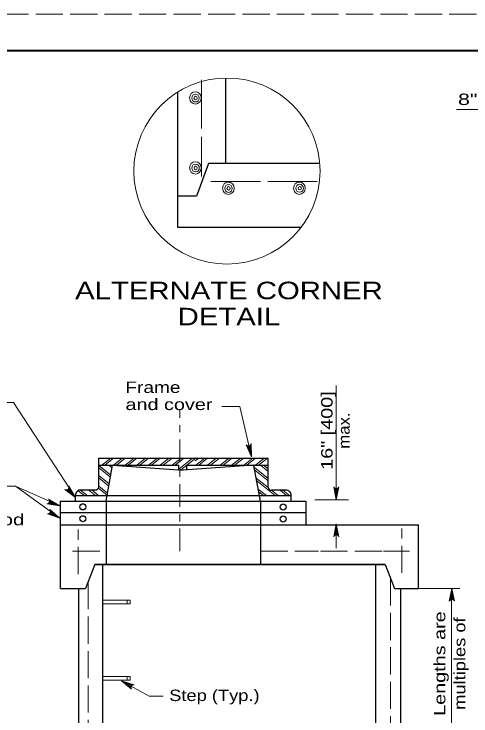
# Model space of a CAD drawing. Extents: x 808.4 to 842.4, y 1034.6 to 1056.6.
# Drawn here: x 819.59 to 825.84, y 1047.01 to 1056.63 of the extents above; entities that cross this region are included whole.
import ezdxf
from ezdxf.enums import TextEntityAlignment as Align

# ---------------------------------------------------------------- set-up
doc = ezdxf.new("R2010")
doc.units = 0
doc.header["$LTSCALE"] = 0.062
doc.linetypes.add('DOT_DASHED', pattern=[7.7, 5, -1.2, 0.3, -1.2])
doc.linetypes.add('LONG_DASHED', pattern=[7.5, 6, -1.5])
doc.layers.add('1', color=7, linetype='Continuous', lineweight=13)
doc.layers.add('10', color=7, linetype='Continuous')

msp = doc.modelspace()

# ---------------------------------------------------------------- linework, layer by layer
at = {"layer": '1', "lineweight": 25}
for p, q in [((822.48142, 1055.75075), (822.48142, 1054.58133)), ((821.82408, 1055.556), (821.82408, 1053.70467)), ((822.48142, 1054.82217), (822.48142, 1054.58133)), ((822.24892, 1054.58133), (822.08375, 1054.1305)), ((822.85492, 1054.58133), (822.24892, 1054.58133)), ((823.77225, 1054.58133), (822.48142, 1054.58133)), ((822.08375, 1054.1305), (821.82958, 1054.1305)), ((821.82408, 1053.70467), (823.517, 1053.70467)), ((820.74533, 1050.14633), (820.74533, 1050.54133)), ((820.74533, 1050.54133), (823.06542, 1050.54133)), ((823.0645, 1050.14258), (823.0645, 1050.54133)), ((820.74533, 1050.445), (821.84467, 1050.445)), ((821.84467, 1050.38208), (821.84467, 1050.445)), ((822.86458, 1050.445), (821.89917, 1050.37792)), ((822.96125, 1049.95075), (822.87183, 1050.44158)), ((820.50092, 1050.1055), (820.69875, 1050.1055)), ((823.30892, 1050.10175), (823.11108, 1050.10175)), ((820.427, 1049.95842), (820.427, 1050.03075)), ((820.427, 1050.03075), (823.38283, 1050.03075)), ((823.38283, 1049.95842), (823.38283, 1050.03075)), ((820.21808, 1049.95408), (820.21808, 1049.62825)), ((820.21808, 1049.95408), (823.58258, 1049.95408)), ((820.846, 1049.9495), (820.84842, 1049.4435)), ((822.96125, 1049.95075), (822.96125, 1049.62825)), ((823.58258, 1049.95075), (823.58258, 1049.62825)), ((820.21808, 1049.79442), (823.58142, 1049.79442)), ((820.21808, 1049.62825), (823.58258, 1049.62825)), ((820.22408, 1049.62808), (824.64392, 1049.62808)), ((822.9615, 1049.62042), (822.9615, 1049.0825)), ((824.64392, 1049.62808), (825.12575, 1049.62808)), ((820.84842, 1049.4435), (820.84842, 1049.09175)), ((820.69325, 1049.0825), (820.56483, 1048.75375)), ((820.69325, 1049.0825), (824.66783, 1049.0825)), ((820.7995, 1049.0825), (820.7995, 1040.04192)), ((824.53808, 1049.0825), (824.53808, 1040.04192)), ((824.66783, 1049.0825), (824.79625, 1048.75375)), ((824.66792, 1049.08242), (824.79625, 1048.75375)), ((820.22408, 1048.75375), (820.56483, 1048.75375)), ((820.47083, 1048.75375), (820.47083, 1046.71117)), ((824.79625, 1048.75375), (825.12575, 1048.75375)), ((824.8835, 1046.71117), (824.88358, 1048.75375))]:
    msp.add_line(p, q, dxfattribs=at)
at = {"layer": '1'}
for p, q in [((822.15117, 1055.72725), (822.15117, 1055.06108)), ((822.15117, 1054.94658), (822.15117, 1054.4015)), ((822.9605, 1054.33233), (822.28067, 1054.33233)), ((823.73567, 1054.33233), (823.06217, 1054.33233)), ((823.99867, 1051.53733), (823.99867, 1049.97233)), ((822.68008, 1051.2515), (822.43017, 1051.2515)), ((822.83842, 1050.56), (822.68008, 1051.2515)), ((822.78167, 1050.71158), (822.83842, 1050.56)), ((822.79367, 1050.70867), (822.83842, 1050.56)), ((822.80508, 1050.7095), (822.83842, 1050.56)), ((822.8185, 1050.71542), (822.83842, 1050.56)), ((822.82733, 1050.72367), (822.83842, 1050.56)), ((820.90933, 1050.54125), (820.78817, 1050.445)), ((820.94875, 1050.53933), (820.83, 1050.445)), ((821.06717, 1050.54075), (820.94658, 1050.445)), ((821.10975, 1050.54133), (820.98842, 1050.445)), ((821.22925, 1050.54125), (821.108, 1050.445)), ((821.26867, 1050.53933), (821.14983, 1050.445)), ((821.387, 1050.54075), (821.26642, 1050.445)), ((821.42958, 1050.54133), (821.30825, 1050.445)), ((821.549, 1050.54125), (821.42775, 1050.445)), ((821.58842, 1050.53933), (821.46967, 1050.445)), ((821.70683, 1050.54075), (821.58625, 1050.445)), ((821.74933, 1050.54133), (821.62808, 1050.445)), ((821.87325, 1050.54117), (821.752, 1050.44492)), ((821.91267, 1050.53925), (821.79392, 1050.44492)), ((822.03108, 1050.54067), (821.84467, 1050.39267)), ((822.07367, 1050.54125), (821.87067, 1050.38008)), ((822.11375, 1050.53883), (822.068, 1050.50258)), ((822.19767, 1050.54117), (822.0765, 1050.44492)), ((822.23708, 1050.53925), (822.11833, 1050.44492)), ((822.3555, 1050.54067), (822.23492, 1050.44492)), ((822.39808, 1050.54125), (822.27675, 1050.44492)), ((822.52317, 1050.53875), (822.402, 1050.4425)), ((822.56258, 1050.53692), (822.44383, 1050.4425)), ((822.681, 1050.53825), (822.56042, 1050.4425)), ((822.72358, 1050.53883), (822.60225, 1050.4425)), ((822.85542, 1050.54125), (822.73417, 1050.445)), ((822.89483, 1050.53933), (822.77608, 1050.445)), ((823.01325, 1050.54075), (822.89267, 1050.445)), ((823.05575, 1050.54133), (822.9345, 1050.445)), ((820.74533, 1050.44125), (820.91167, 1050.30933)), ((820.88175, 1050.44417), (820.92883, 1050.40675)), ((820.92208, 1050.44417), (820.93442, 1050.43442)), ((822.96092, 1050.44375), (823.06375, 1050.36217)), ((823.00008, 1050.4445), (823.0645, 1050.39325)), ((820.74533, 1050.40808), (820.90633, 1050.28017)), ((822.87733, 1050.4115), (823.06508, 1050.26233)), ((822.88392, 1050.37533), (823.06508, 1050.2315)), ((820.74533, 1050.303), (820.88958, 1050.18858)), ((820.74558, 1050.26967), (820.88433, 1050.15942)), ((822.9035, 1050.268), (823.06483, 1050.13983)), ((820.21375, 1049.7195), (819.60567, 1050.15742)), ((820.74658, 1050.1575), (820.86692, 1050.06208)), ((822.9125, 1050.229), (823.16283, 1050.03017)), ((820.3015, 1050.10658), (820.42717, 1050.00117)), ((820.31333, 1050.10883), (820.42717, 1050.00117)), ((820.326, 1050.11617), (820.42717, 1050.00117)), ((820.33342, 1050.12492), (820.42717, 1050.00117)), ((820.33817, 1050.13633), (820.42717, 1050.00117)), ((820.46267, 1050.0955), (820.5425, 1050.03208)), ((820.49167, 1050.10567), (820.58667, 1050.03025)), ((820.61, 1050.10433), (820.70292, 1050.0305)), ((820.64942, 1050.10617), (820.74417, 1050.031)), ((820.741, 1050.12875), (820.86075, 1050.03367)), ((822.93067, 1050.11808), (823.04133, 1050.03025)), ((822.93758, 1050.08083), (823.00083, 1050.03067)), ((823.11342, 1050.10117), (823.20283, 1050.03017)), ((823.22958, 1050.10075), (823.31842, 1050.03017)), ((823.26675, 1050.10208), (823.35733, 1050.03017)), ((823.97625, 1050.13258), (823.99867, 1049.97233)), ((823.98733, 1050.12717), (823.99867, 1049.97233)), ((824.0235, 1050.1345), (823.99867, 1049.97233)), ((824.01308, 1050.12833), (823.99867, 1049.97233)), ((823.99867, 1050.1255), (823.99867, 1049.97233)), ((820.07067, 1049.96342), (820.21367, 1049.88767)), ((823.70383, 1049.97233), (824.16483, 1049.97233)), ((820.05283, 1049.91975), (820.21367, 1049.88767)), ((820.06208, 1049.92742), (820.21367, 1049.88767)), ((820.06967, 1049.93992), (820.21367, 1049.88767)), ((820.072, 1049.95117), (820.21367, 1049.88767)), ((820.06067, 1049.77833), (820.21375, 1049.7195)), ((820.07108, 1049.78433), (820.21375, 1049.7195)), ((820.08075, 1049.79542), (820.21375, 1049.7195)), ((820.08492, 1049.80608), (820.21375, 1049.7195)), ((820.08567, 1049.81842), (820.21375, 1049.7195)), ((823.97392, 1049.48), (823.99867, 1049.64217)), ((823.98433, 1049.48617), (823.99867, 1049.64217)), ((823.99867, 1049.489), (823.99867, 1049.64217)), ((824.01, 1049.48733), (823.99867, 1049.64217)), ((824.02108, 1049.48192), (823.99867, 1049.64217)), ((823.99867, 1049.64217), (823.99867, 1049.30933)), ((824.97742, 1048.75675), (825.69158, 1048.75675)), ((825.19625, 1048.75675), (825.69158, 1048.75675)), ((825.55725, 1048.59492), (825.582, 1048.757)), ((825.56767, 1048.601), (825.582, 1048.757)), ((825.5775, 1048.75675), (825.5775, 1046.73775)), ((825.582, 1048.60383), (825.582, 1048.757)), ((825.59333, 1048.60225), (825.582, 1048.757)), ((825.60442, 1048.59683), (825.582, 1048.757)), ((820.79992, 1048.59592), (821.178, 1048.59592)), ((820.79992, 1048.543), (821.178, 1048.543)), ((821.13425, 1048.54217), (821.13425, 1048.59508)), ((821.178, 1048.543), (821.178, 1048.59592)), ((820.79992, 1047.54975), (821.178, 1047.54975)), ((820.79992, 1047.49675), (821.178, 1047.49675)), ((821.19217, 1047.41658), (821.05833, 1047.49117)), ((821.18767, 1047.40267), (821.05833, 1047.49117)), ((821.18792, 1047.39058), (821.05833, 1047.49117)), ((821.19908, 1047.42567), (821.05833, 1047.49117)), ((821.20925, 1047.43275), (821.05833, 1047.49117)), ((821.05833, 1047.49117), (821.43758, 1047.27942)), ((821.13408, 1047.49658), (821.13408, 1047.5495)), ((821.178, 1047.49675), (821.178, 1047.54975)), ((821.43758, 1047.27933), (821.62633, 1047.27933))]:
    msp.add_line(p, q, dxfattribs=at)
at = {"layer": '1', "linetype": 'DOT_DASHED'}
msp.add_line((821.85792, 1049.26533), (821.85792, 1051.19467), dxfattribs=at)
at = {"layer": '1', "linetype": 'LONG_DASHED'}
for p, q in [((820.38767, 1049.26492), (820.847, 1049.26492)), ((822.9615, 1049.26492), (823.75675, 1049.26492)), ((823.782, 1049.26492), (824.64392, 1049.26492)), ((824.64392, 1049.26492), (825.00358, 1049.26492)), ((820.59942, 1048.84225), (820.59942, 1044.61292)), ((824.74183, 1048.89308), (824.74183, 1044.64242))]:
    msp.add_line(p, q, dxfattribs=at)
msp.add_lwpolyline([(808.43883, 1034.62767), (842.43883, 1034.62767), (842.43883, 1056.62767), (808.43883, 1056.62767)], close=True, dxfattribs=at)
at = {"layer": '1', "lineweight": 25}
msp.add_lwpolyline([(810.43883, 1056.12767), (841.93883, 1056.12767), (841.93883, 1035.12767), (810.43883, 1035.12767)], close=True, dxfattribs=at)
at = {"layer": '1', "lineweight": 40}
msp.add_lwpolyline([(810.43883, 1056.12767), (841.93883, 1056.12767), (841.93883, 1035.12767), (810.43883, 1035.12767)], close=True, dxfattribs=at)
at = {"layer": '1'}
for points in [[(825.64475, 1055.31858), (829.13883, 1055.31858), (831.39858, 1055.31858)], [(820.42717, 1050.00117), (819.57933, 1051.30342), (819.32275, 1051.30342)], [(822.83442, 1050.7405), (822.83842, 1050.56), (822.76533, 1050.72508)], [(820.21367, 1049.88767), (819.60567, 1050.15742), (819.29283, 1050.15742)], [(820.28367, 1050.11075), (820.42717, 1050.00117), (820.33683, 1050.1575)], [(824.03408, 1050.14933), (823.99867, 1049.97233), (823.96333, 1050.14933)], [(820.03517, 1049.91483), (820.21367, 1049.88767), (820.05933, 1049.98133)], [(820.0425, 1049.7765), (820.21375, 1049.7195), (820.07758, 1049.838)], [(823.96333, 1049.46517), (823.99867, 1049.64217), (824.03408, 1049.46517)], [(825.54667, 1048.58), (825.582, 1048.757), (825.61742, 1048.58)], [(821.19575, 1047.37408), (821.05833, 1047.49117), (821.23025, 1047.43592)]]:
    msp.add_lwpolyline(points, dxfattribs=at)
at = {"layer": '1', "lineweight": 25}
for points in [[(820.847, 1049.95408), (820.93633, 1050.445), (821.90075, 1050.378)], [(821.95308, 1050.37975), (821.95308, 1050.445), (823.06542, 1050.445)], [(820.22408, 1048.75375), (820.22408, 1049.4435), (820.22408, 1049.62808)], [(825.12575, 1048.75375), (825.12575, 1049.4435), (825.12575, 1049.62808)], [(824.66817, 1049.0825), (820.69325, 1049.0825), (820.56483, 1048.75375)]]:
    msp.add_lwpolyline(points, dxfattribs=at)
at = {"layer": '1', "linetype": 'LONG_DASHED'}
for points in [[(824.89742, 1048.96808), (824.89742, 1049.4435), (824.89742, 1049.57867)], [(820.46425, 1048.95208), (820.46425, 1049.4435), (820.46425, 1049.56267)]]:
    msp.add_lwpolyline(points, dxfattribs=at)
at = {"layer": '1'}
msp.add_circle((822.50162, 1054.47589), 1.27504, dxfattribs=at)
for centre, start, end in [((822.79679, 1050.74672), 214.66476, 350.49089), ((820.30088, 1050.14487), 243.40718, 19.23331), ((823.99866, 1050.16366), 202.08782, 337.91395), ((820.03386, 1049.953), 272.12644, 47.95256), ((820.04762, 1049.81438), 262.36834, 38.19447), ((823.99874, 1049.45085), 22.08782, 157.91395), ((825.58207, 1048.56574), 22.08782, 157.91395), ((821.22549, 1047.39807), 82.95756, 218.78369)]:
    msp.add_arc(centre, 0.0382, start, end, dxfattribs=at)
for centre, major_axis in [((822.06934, 1055.47798), (0, 0.08465)), ((822.07099, 1055.47665), (0, 0.05431)), ((822.07225, 1055.47673), (0, 0.0237)), ((822.07013, 1054.51903), (0, 0.08465)), ((822.07178, 1054.5177), (0, 0.05431)), ((822.07304, 1054.51778), (0, 0.0237)), ((822.52128, 1054.23969), (0, 0.08465)), ((822.52293, 1054.23836), (0, 0.05431)), ((823.4936, 1054.23969), (0, 0.08465)), ((823.49667, 1054.24003), (0, 0.05431)), ((822.52419, 1054.23844), (0, 0.0237)), ((823.49793, 1054.24011), (0, 0.0237))]:
    msp.add_ellipse(centre, major_axis=major_axis, ratio=0.944544, dxfattribs=at)
at = {"layer": '1', "lineweight": 25}
for centre, major_axis, start_param, end_param in [((820.49754, 1050.03092), (0, 0.0747), 6.2351802, 7.8562929), ((820.70398, 1050.14906), (0, -0.04387), 6.1570556, 7.7921271), ((823.10587, 1050.14531), (0, -0.04387), 4.7742435, 6.409315), ((823.31232, 1050.02717), (0, 0.0747), 4.7100777, 6.3311904)]:
    msp.add_ellipse(centre, major_axis=major_axis, ratio=0.944544, start_param=start_param, end_param=end_param, dxfattribs=at)
for centre in [(820.52814, 1049.87434), (823.27125, 1049.87092), (820.52814, 1049.71052), (823.27125, 1049.7071)]:
    msp.add_ellipse(centre, major_axis=(0, 0.04232), ratio=0.944544, dxfattribs=at)

# ---------------------------------------------------------------- texts
at = {"layer": '10'}
for s, width, p in [('8" [200]', 1.4, (825.66608, 1055.38092)), ('Frame', 1.25, (821.112, 1051.43508)), ('and cover', 1.3, (821.112, 1051.20042)), ('approved method ', 1.35, (817.53625, 1049.62133)), ('Step (Typ.)', 1.2, (821.71067, 1047.21283))]:
    msp.add_text(s, height=0.156, dxfattribs=dict(at, width=width)).set_placement(p)
at = {"layer": '10', "width": 1.25}
for s, p in [('ALTERNATE CORNER', (822.52883, 1052.71942)), ('DETAIL', (822.52887, 1052.36142))]:
    msp.add_text(s, height=0.24, dxfattribs=at).set_placement(p, align=Align.CENTER)
at = {"layer": '10'}
for s, width, p in [('16" [400]', 1.3, (823.94775, 1050.91929)), ('max.', 1.1, (824.18242, 1050.91925)), ('Lengths are', 1.3, (825.4925, 1047.72604)), ('multiples of', 1.2, (825.7665, 1047.72604))]:
    msp.add_text(s, height=0.156, rotation=90, dxfattribs=dict(at, width=width)).set_placement(p, align=Align.CENTER)

doc.saveas('drawing.dxf')
